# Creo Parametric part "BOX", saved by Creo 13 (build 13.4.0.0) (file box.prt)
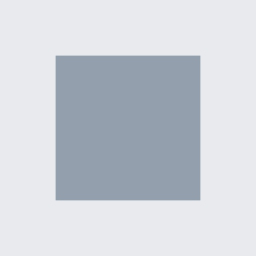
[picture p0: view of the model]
Units: millimeter Newton Second (mmNs); MM, TONNE, SECS

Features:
  1. datum plane "RIGHT"
  2. datum plane "TOP"
  3. datum plane "FRONT"
  4. coordinate system
  5. protrusion
  6. datum axis

Surfaces: 6 plane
